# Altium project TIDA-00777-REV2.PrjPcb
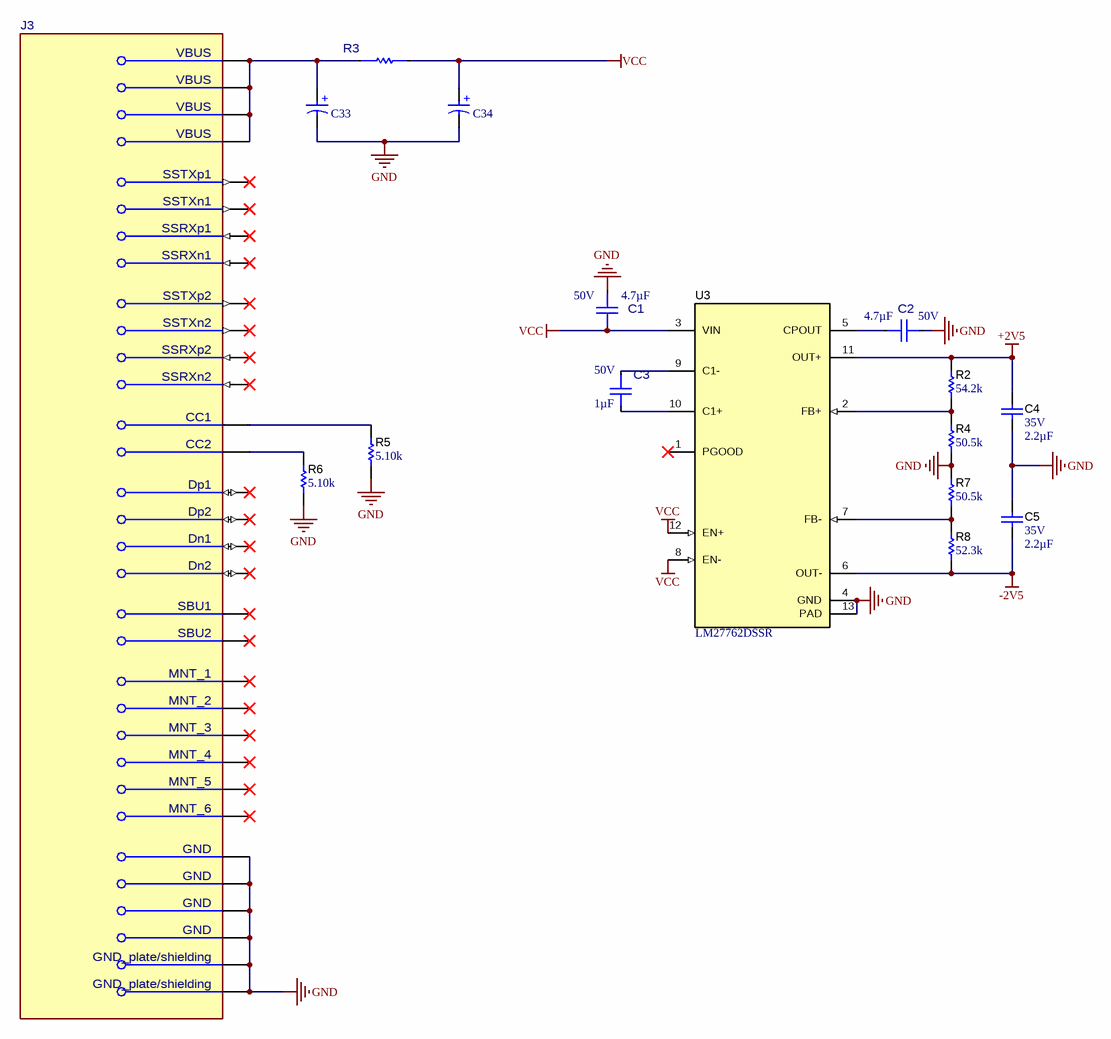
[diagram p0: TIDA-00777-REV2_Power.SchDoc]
CopyrightYear: 2018; PCB_Layout: Who did the Layout?; PCB_Rev: E1; PRJ_Customer: Public Release; PRJ_Engineer: Enter name of project lead; PRJ_Number: XXX###; PRJ_Title: Change in menu Project|Project Options|Parameters; SCH_Rev: E1; TechSupport: http://www.ti.com/support; TID: N/A
2 sheets, 105 parts. Net scope: global (net labels, ports and power ports of the same name join across sheets).
Board file: TIDA-00777-REV2.PcbDoc
Sheets:
  TIDA-00777-REV2_Power.SchDoc
  TIDA-00777-REV2_AFE.SchDoc

## Sheet TIDA-00777-REV2_Power.SchDoc
size 431 x 279 mm; Date: Not shown in title block; ApprovedBy: Not shown in title block; CheckedBy: Not shown in title block; Author: Not shown in title block; CompanyName: Not shown in title block; Engineer: Not shown in title block; Organization: Not shown in title block; Address1: Not shown in title block; Address2: Not shown in title block; Address3: Not shown in title block; Address4: Not shown in title block; DocumentNumber: 2; Revision: Use project parameter SCH_Rev; SheetNumber: 2; SheetTotal: 4; PageSetup: Record=PageOptions¦CenterHorizontal=True¦CenterVertical=True¦PrintScale=1.00¦XCorrection=1.00¦YCorrection=1.00¦PrintKind=0¦BorderSize=5000000¦LeftOffset=0¦BottomOffset=0¦Orientation=2¦PaperLength=1000¦PaperWidth=1000¦Scale=100¦PaperSource=15¦PrintQuality=600¦MediaType=1¦DitherType=10¦PaperKind=Letter¦PrintScaleMode=1

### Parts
(Parts that share a designator on the sheet are numbered #1, #2 ... from top to bottom, then left to right.)
C1  Cap_F: 4.7µF  VDC_V: 50V  [FP-CGA4J1X7R1H475K125AC_0805-MFG]  (hidden comment: CGA4J1X7R1H475K125AC)
C2  Cap_F: 4.7µF  VDC_V: 50V  [FP-CGA4J1X7R1H475K125AC_0805-MFG]  (hidden comment: CGA4J1X7R1H475K125AC)
C3  VDC_V: 50V  Cap_F: 1µF  [FP-GMC10X7R105K50NT_0603-MFG]  (hidden comment: GMC10X7R105K50NT)
C4  VDC_V: 35V  Cap_F: 2.2µF  [0603]  (hidden comment: C1608X5R1V225K080AC)
C5  VDC_V: 35V  Cap_F: 2.2µF  [0603]  (hidden comment: C1608X5R1V225K080AC)
C33  860020572003  [WCAP-ATG5_D5H11]  (value not drawn)
C34  860020572003  [WCAP-ATG5_D5H11]  (value not drawn)
J3#1  632723300011  [FP-632723300011_CONN_USB_8MM74_11MM20-MFG]  (value not drawn)
R2  ValueDisplayed: 54.2k  [0603]  (hidden comment: RT0603BRD0754K2L)
R3  RC0603JR-130RP  [FP-RC0603JR-130RP_0603-MFG]  (value not drawn)
R4  ValueDisplayed: 50.5k  [0603]  (hidden comment: RT0603DRE0750K5L)
R5  ValueDisplayed: 5.10k  [0603]  (hidden comment: RG1608P-512-B-T5)
R6  ValueDisplayed: 5.10k  [0603]  (hidden comment: RG1608P-512-B-T5)
R7  ValueDisplayed: 50.5k  [0603]  (hidden comment: RT0603DRE0750K5L)
R8  ValueDisplayed: 52.3k  [0603]  (hidden comment: RT0603BRD0752K3L)
U3  LM27762DSSR  [DSS0012B]

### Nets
+2V5: C4.1 R2.1 U3.11(OUT+)
-2V5: C5.2 R8.2 U3.6(OUT-)
GND: C1.1 C2.2 C4.2 C5.1 C33.2(N) C34.2(N) J3#1.1(GND_plate/shielding) J3#1.2(GND_plate/shielding) J3#1.A1(GND) J3#1.A12(GND) J3#1.B1(GND) J3#1.B12(GND) R4.1 R5.2 R6.2 R7.2 U3.4(GND) U3.13(PAD)
VCC: C1.2 C34.1(P) R3.2 U3.3(VIN) U3.8(EN-) U3.12(EN+)
NetC2_1: C2.1 U3.5(CPOUT)
NetC3_1: C3.1 U3.9(C1-)
NetC3_2: C3.2 U3.10(C1+)
NetC33_1: C33.1(P) J3#1.A4(VBUS) J3#1.A9(VBUS) J3#1.B4(VBUS) J3#1.B9(VBUS) R3.1
NetJ3#1_A5: J3#1.A5(CC1) R5.1
NetJ3#1_B5: J3#1.B5(CC2) R6.1
NetR2_2: R2.2 R4.2 U3.2(FB+)
NetR7_1: R7.1 R8.1 U3.7(FB-)

Not connected (* = marked no-connect by the designer): J3#1 3(MNT_1)* 4(MNT_2)* 5(MNT_3)* 6(MNT_4)* 7(MNT_5)* 8(MNT_6)* A2(SSTXp1)* A3(SSTXn1)* A6(Dp1)* A7(Dn1)* A8(SBU1)* A10(SSRXn2)* A11(SSRXp2)* B2(SSTXp2)* B3(SSTXn2)* B6(Dp2)* B7(Dn2)* B8(SBU2)* B10(SSRXn1)* B11(SSRXp1)*; U3 1(PGOOD)*

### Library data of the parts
C1 C2 = CMP-0090082-1: Cap Ceramic 4.7uF 50V X7R 10% Pad SMD 0805 +125°C Automotive T/R; Manufacturer: TDK Corporation; TempCo: 15%; Value: 4.7µF; Tolerance_%: 0.1%; SizeZ_mm: 1.45mm; AEC Qualified: Yes; AEC Grade: Grade 1
C3 = CMP-0095295-1: 1 µF ±10% 50V Ceramic Capacitor X7R 0603 (1608 Metric); Manufacturer: Cal-Chip Electronics; TempCo: 30ppm/°C; Value: 1µF; SizeZ_mm: 1mm; AEC Qualified: No; ValueDisplayed: 1uF
C4 C5 = CMP-0007020-5: CAP, CERM, 2.2 uF, 35 V, +/- 10%, X5R, 0603; Manufacturer: TDK; TaMin_C: -55°C; Polarized: N; SizeAreaWB_mm2: 4.68; Value1: 0.007674 ohm; U/M: EA; Value: 2.2uF; TaMax_C: 85°C; SizeZ_mm: 1; SizeX_mm: 1.6; SizeY_mm: 0.8; SizeArea_mm2: 1.28; AEC Category: Q200; ESR_ohm: 7.674m; IRMS_A: 1.8782A
C33 C34 = CMP-0109532-1: WCAP-ATG5 Aluminum Electrolytic Capacitor, Radial, THT, D5 x H11mm, 10µF, 35V; Manufacturer: Wurth Elektronik; Capacitance Tolerance: +/-20%; Dissipation Factor: 12%; Endurance: 2000h; Leakage Current: 3.5uA; Ripple Current: 46mA; Technical Reference: ATDC110100M035DSPA3B000
J3#1 = CMP-0091586-1: USB-C (USB TYPE-C) USB 3.2 Gen 2 (USB 3.1 Gen 2, Superspeed + (USB 3.1)) Receptacle Connector 24 Position Surface Mount, Right Angle; Through Hole; Manufacturer: Wurth; AEC Qualified: No; Shrouded: true; SizeZ_mm: 3.41mm; Is Female: yes; Usb Standard: USB 3.1; Voltage_V: 20V; ContactFinish: Gold,Nickel; Conn Orientation: Horizontal; Standoff Height: 0.1mm; Current_A: 5A
R2 = CMP-0024333-2: RES, 54.2 k, 0.1%, 0.1 W, 0603; Manufacturer: Yageo America; Power_W: 100mW; TempCo: 25 ppm/C; Value_Code: 54k2; Value: 54.2k; EIA_Code: E192; SizeX_mm: 1.6; SizeY_mm: 0.8; SizeZ_mm: 1; Value2: 0.1W; SizeArea_mm2: 1.28; VDC_V: 75V; AEC Category: Q200; U/M: EA
R3 = CMP-0120804-1: Resistor Thick Film 0603 Jumper 0 Ohm ±5% 1/10W Molded Paper T/R; Manufacturer: Yageo; Power_W: 100mW; Value: 0; SizeZ_mm: 0.55mm; AEC Qualified: No; VDC_V: 75V
R4 R7 = CMP-0025375-2: RES, 50.5 k, 0.5%, 0.1 W, 0603; Manufacturer: Yageo America; Power_W: 100mW; TempCo: 50 ppm/C; Value_Code: 50k5; U/M: EA; Value: 50.5k; EIA_Code: E192; SizeX_mm: 1.6; SizeY_mm: 0.8; SizeZ_mm: 1; Value2: 0.1W; SizeArea_mm2: 1.28; VDC_V: 75V; AEC Category: Q200
R5 R6 = CMP-0023568-3: RES, 5.10 k, 0.1%, 0.1 W, 0603; Manufacturer: Susumu Co Ltd; Power_W: 100mW; TempCo: 25 ppm/C; Value_Code: 5k10; Value: 5.10k; Res_ohm: 5.1k; SizeX_mm: 1.6; SizeY_mm: 0.8; SizeZ_mm: 1; Value2: 0.1W; SizeArea_mm2: 1.28; VDC_V: 75V; AEC Category: Q200; U/M: EA
R8 = CMP-0024319-3: RES, 52.3 k, 0.1%, 0.1 W, 0603; Manufacturer: Yageo America; Power_W: 100mW; TempCo: 25 ppm/C; Value_Code: 52k3; U/M: EA; Value: 52.3k; EIA_Code: E192; SizeX_mm: 1.6; SizeY_mm: 0.8; SizeZ_mm: 1; Value2: 0.1W; SizeArea_mm2: 1.28; VDC_V: 75V; AEC Category: Q200
U3 = CMP-0076280-3: Low-Noise Positive- and Negative-Output Charge Pump With Integrated LDO, DSS0012B (WSON-12); Alternate PartNumber: LM27762DSST; Alternate Manufacturer: Texas Instruments; SizeZ_mm: 0.8; SizeArea_mm2: 6.0; AEC Qualified: N; Rating: Catalog; SizeY_mm: 3.0; SizeX_mm: 2.0; CompType: IC; AEC Category: Q200; SizeAreaWB_mm2: 12.0

## Sheet TIDA-00777-REV2_AFE.SchDoc
size 431 x 279 mm; Date: Not shown in title block; ApprovedBy: Not shown in title block; CheckedBy: Not shown in title block; Author: Not shown in title block; CompanyName: Not shown in title block; Engineer: Not shown in title block; Organization: Not shown in title block; Address1: Not shown in title block; Address2: Not shown in title block; Address3: Not shown in title block; Address4: Not shown in title block; DocumentNumber: 2; Revision: Use project parameter SCH_Rev; SheetNumber: 3; SheetTotal: 4; PageSetup: Record=PageOptions¦CenterHorizontal=True¦CenterVertical=True¦PrintScale=1.00¦XCorrection=1.00¦YCorrection=1.00¦PrintKind=0¦BorderSize=5000000¦LeftOffset=0¦BottomOffset=0¦Orientation=2¦PaperLength=1000¦PaperWidth=1000¦Scale=100¦PaperSource=15¦PrintQuality=600¦MediaType=1¦DitherType=10¦PaperKind=Letter¦PrintScaleMode=1
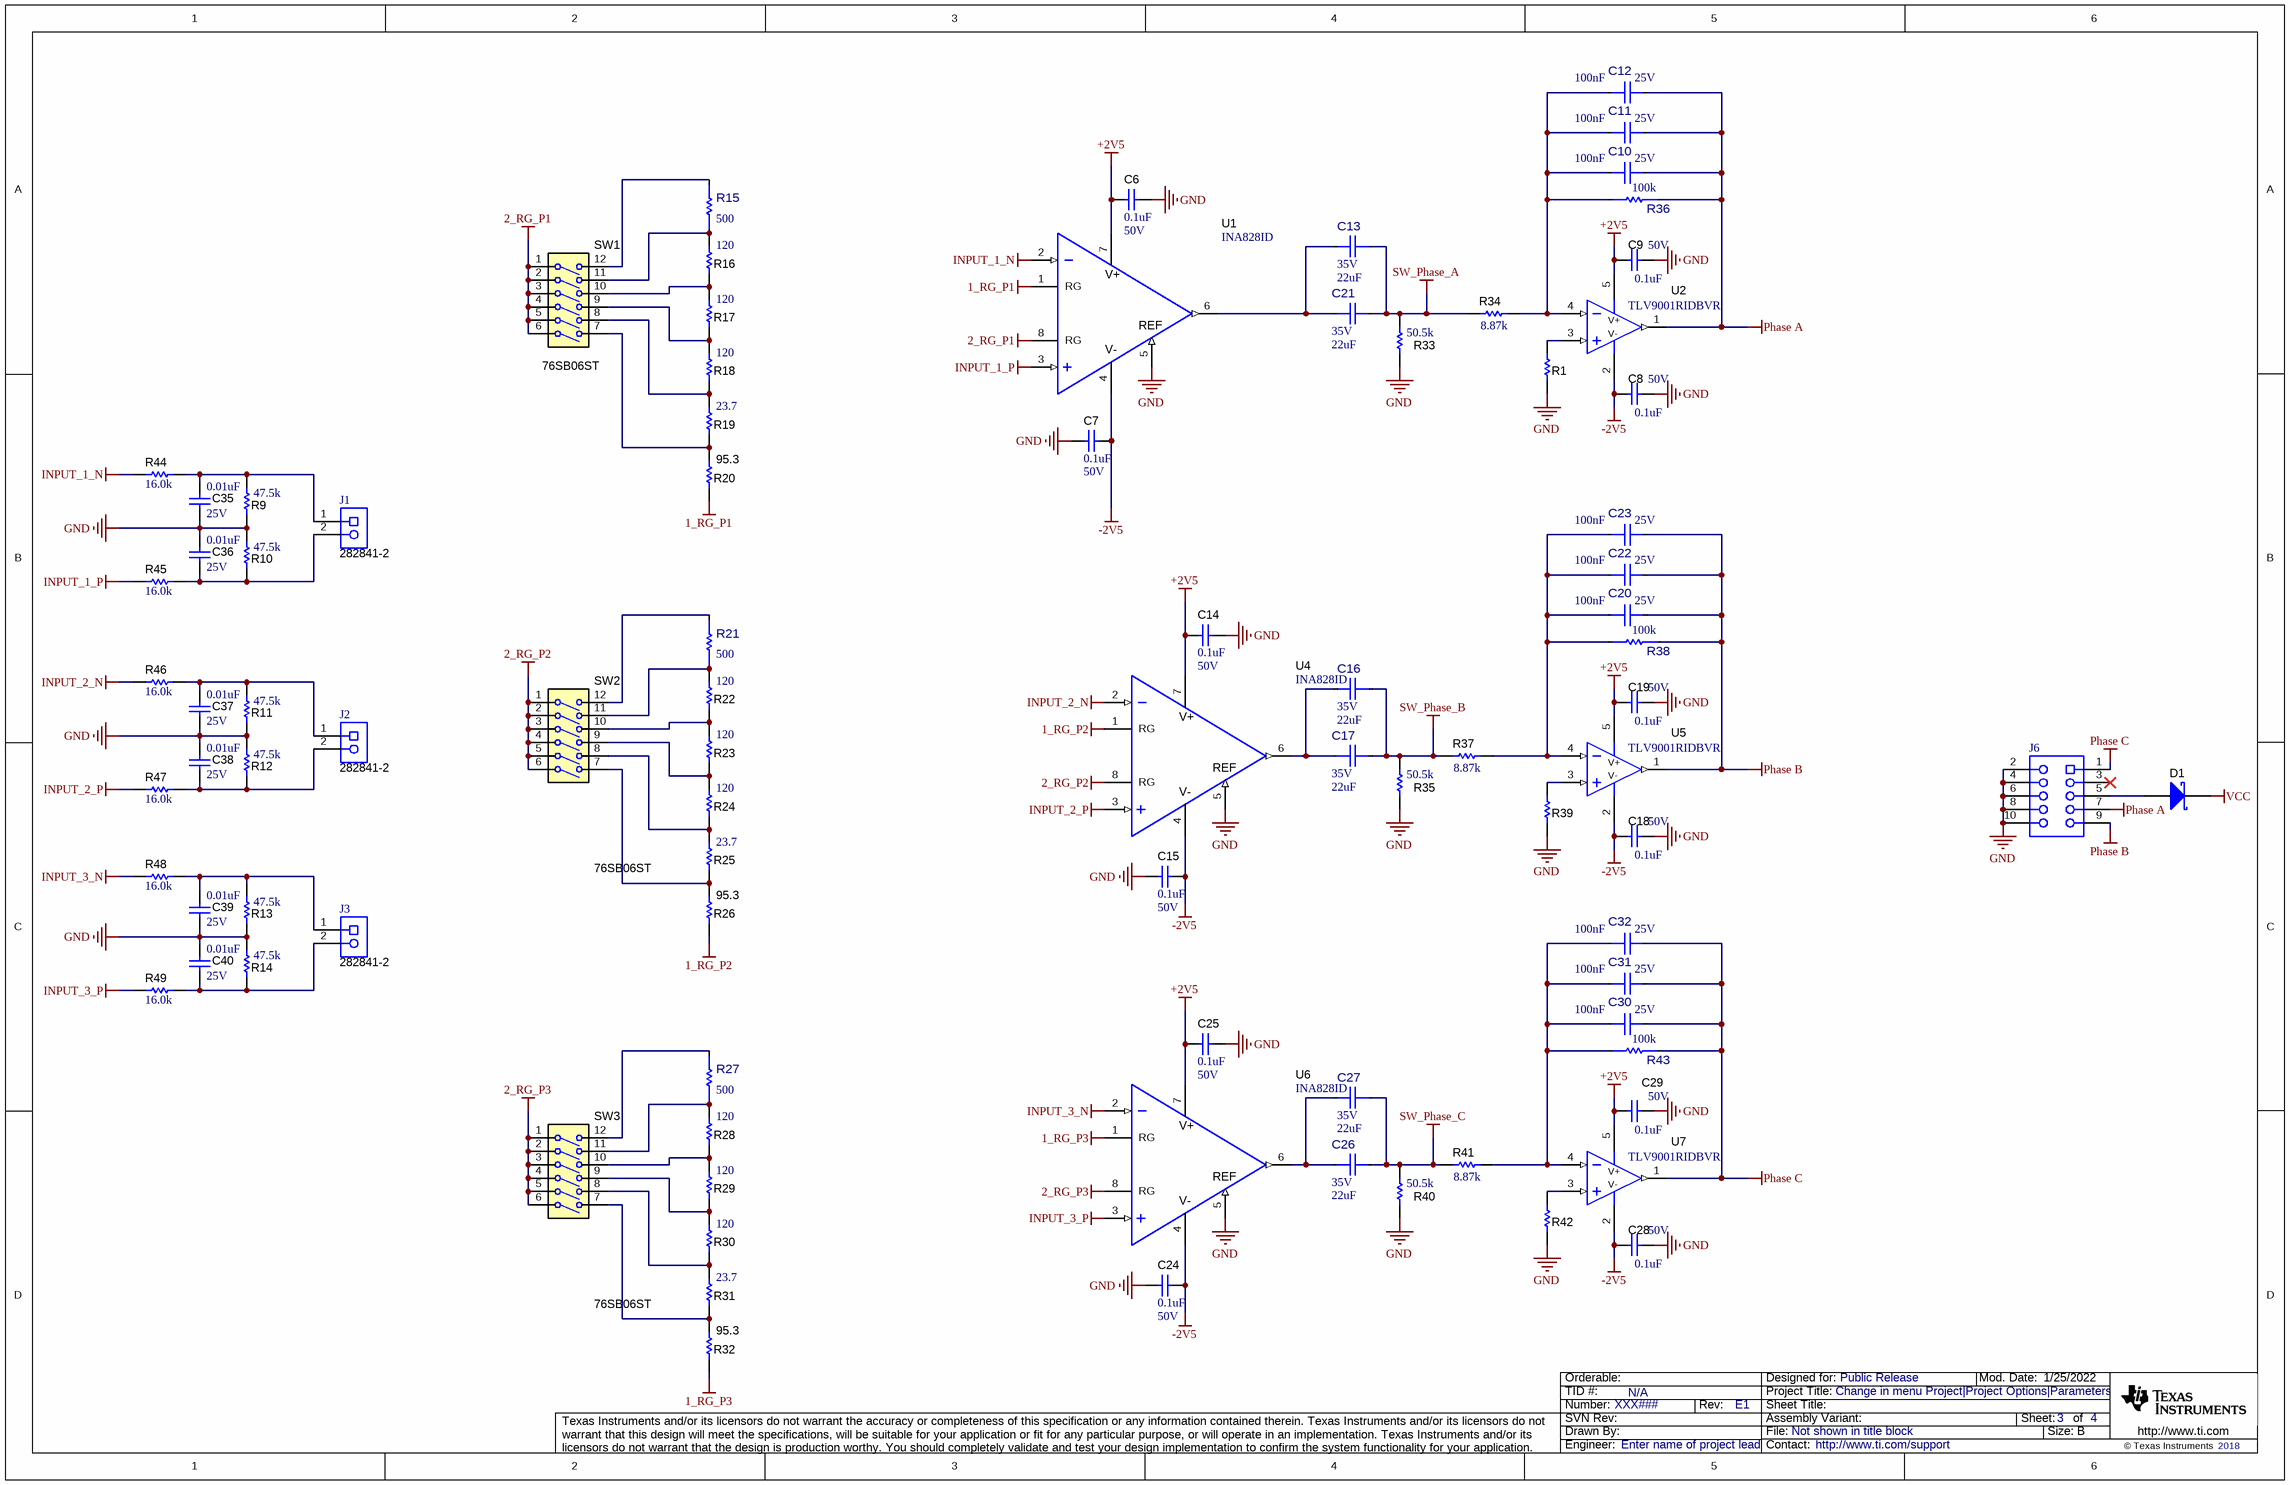
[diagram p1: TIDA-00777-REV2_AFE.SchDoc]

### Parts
(Parts that share a designator on the sheet are numbered #1, #2 ... from top to bottom, then left to right.)
C6  value 0.1uF  VDC_V: 50V  [0603]  (hidden comment: 06035C104JAT2A)
C7  value 0.1uF  VDC_V: 50V  [0603]  (hidden comment: 06035C104JAT2A)
C8  value 0.1uF  VDC_V: 50V  [0603]  (hidden comment: 06035C104JAT2A)
C9  value 0.1uF  VDC_V: 50V  [0603]  (hidden comment: 06035C104JAT2A)
C10  value 100nF  VDC_V: 25V  [FP-AC0805KRX7R8BB104_0805-MFG]  (hidden comment: AC0805KRX7R8BB104)
C11  value 100nF  VDC_V: 25V  [FP-AC0805KRX7R8BB104_0805-MFG]  (hidden comment: AC0805KRX7R8BB104)
C12  value 100nF  VDC_V: 25V  [FP-AC0805KRX7R8BB104_0805-MFG]  (hidden comment: AC0805KRX7R8BB104)
C13  VDC_V: 35V  ValueDisplayed: 22uF  [FP-GMC21X5R226M35NT_0805-MFG]  (hidden comment: GMC21X5R226M35NT)
C14  value 0.1uF  VDC_V: 50V  [0603]  (hidden comment: 06035C104JAT2A)
C15  value 0.1uF  VDC_V: 50V  [0603]  (hidden comment: 06035C104JAT2A)
C16  VDC_V: 35V  ValueDisplayed: 22uF  [FP-GMC21X5R226M35NT_0805-MFG]  (hidden comment: GMC21X5R226M35NT)
C17  VDC_V: 35V  ValueDisplayed: 22uF  [FP-GMC21X5R226M35NT_0805-MFG]  (hidden comment: GMC21X5R226M35NT)
C18  value 0.1uF  VDC_V: 50V  [0603]  (hidden comment: 06035C104JAT2A)
C19  value 0.1uF  VDC_V: 50V  [0603]  (hidden comment: 06035C104JAT2A)
C20  value 100nF  VDC_V: 25V  [FP-AC0805KRX7R8BB104_0805-MFG]  (hidden comment: AC0805KRX7R8BB104)
C21  VDC_V: 35V  ValueDisplayed: 22uF  [FP-GMC21X5R226M35NT_0805-MFG]  (hidden comment: GMC21X5R226M35NT)
C22  value 100nF  VDC_V: 25V  [FP-AC0805KRX7R8BB104_0805-MFG]  (hidden comment: AC0805KRX7R8BB104)
C23  value 100nF  VDC_V: 25V  [FP-AC0805KRX7R8BB104_0805-MFG]  (hidden comment: AC0805KRX7R8BB104)
C24  value 0.1uF  VDC_V: 50V  [0603]  (hidden comment: 06035C104JAT2A)
C25  value 0.1uF  VDC_V: 50V  [0603]  (hidden comment: 06035C104JAT2A)
C26  VDC_V: 35V  ValueDisplayed: 22uF  [FP-GMC21X5R226M35NT_0805-MFG]  (hidden comment: GMC21X5R226M35NT)
C27  VDC_V: 35V  ValueDisplayed: 22uF  [FP-GMC21X5R226M35NT_0805-MFG]  (hidden comment: GMC21X5R226M35NT)
C28  value 0.1uF  VDC_V: 50V  [0603]  (hidden comment: 06035C104JAT2A)
C29  value 0.1uF  VDC_V: 50V  [0603]  (hidden comment: 06035C104JAT2A)
C30  value 100nF  VDC_V: 25V  [FP-AC0805KRX7R8BB104_0805-MFG]  (hidden comment: AC0805KRX7R8BB104)
C31  value 100nF  VDC_V: 25V  [FP-AC0805KRX7R8BB104_0805-MFG]  (hidden comment: AC0805KRX7R8BB104)
C32  value 100nF  VDC_V: 25V  [FP-AC0805KRX7R8BB104_0805-MFG]  (hidden comment: AC0805KRX7R8BB104)
C35  value 0.01uF  VDC_V: 25V  [0603]  (hidden comment: C0603H103J3GACTU)
C36  value 0.01uF  VDC_V: 25V  [0603]  (hidden comment: C0603H103J3GACTU)
C37  value 0.01uF  VDC_V: 25V  [0603]  (hidden comment: C0603H103J3GACTU)
C38  value 0.01uF  VDC_V: 25V  [0603]  (hidden comment: C0603H103J3GACTU)
C39  value 0.01uF  VDC_V: 25V  [0603]  (hidden comment: C0603H103J3GACTU)
C40  value 0.01uF  VDC_V: 25V  [0603]  (hidden comment: C0603H103J3GACTU)
D1  SD103AWS-7-F  [SOD-323]  (value not drawn)
J1  282841-2  [TEC_282841-2]
J2  282841-2  [TEC_282841-2]
J3#2  282841-2  [TEC_282841-2]
J6  SFH11-PBPC-D05-RA-BK  [Sullins_SFH11-PBPC-D05-RA-BK]  (value not drawn)
R1  RT0603BRD079K88L  [0603]  (value not drawn)
R9  value 47.5k  [0603]  (hidden comment: RT0603BRD0747K5L)
R10  value 47.5k  [0603]  (hidden comment: RT0603BRD0747K5L)
R11  value 47.5k  [0603]  (hidden comment: RT0603BRD0747K5L)
R12  value 47.5k  [0603]  (hidden comment: RT0603BRD0747K5L)
R13  value 47.5k  [0603]  (hidden comment: RT0603BRD0747K5L)
R14  value 47.5k  [0603]  (hidden comment: RT0603BRD0747K5L)
R15  value 500  [FP-MCT06030D5000BP100_0603-MFG]  (hidden comment: MCT06030D5000BP100)
R16  value 120  [0603]  (hidden comment: RT0603BRD07120RL)
R17  value 120  [0603]  (hidden comment: RT0603BRD07120RL)
R18  value 120  [0603]  (hidden comment: RT0603BRD07120RL)
R19  value 23.7  [0603]  (hidden comment: RT0603BRD0723R7L)
R20  95.3  [0603]
R21  value 500  [FP-MCT06030D5000BP100_0603-MFG]  (hidden comment: MCT06030D5000BP100)
R22  value 120  [0603]  (hidden comment: RT0603BRD07120RL)
R23  value 120  [0603]  (hidden comment: RT0603BRD07120RL)
R24  value 120  [0603]  (hidden comment: RT0603BRD07120RL)
R25  value 23.7  [0603]  (hidden comment: RT0603BRD0723R7L)
R26  95.3  [0603]
R27  value 500  [FP-MCT06030D5000BP100_0603-MFG]  (hidden comment: MCT06030D5000BP100)
R28  value 120  [0603]  (hidden comment: RT0603BRD07120RL)
R29  value 120  [0603]  (hidden comment: RT0603BRD07120RL)
R30  value 120  [0603]  (hidden comment: RT0603BRD07120RL)
R31  value 23.7  [0603]  (hidden comment: RT0603BRD0723R7L)
R32  95.3  [0603]
R33  value 50.5k  [0603]  (hidden comment: RT0603BRD0750K5L)
R34  value 8.87k  [0603]  (hidden comment: RT0603BRD078K87L)
R35  value 50.5k  [0603]  (hidden comment: RT0603BRD0750K5L)
R36  value 100k  [FP-ERA-3AEB104V_0603-MFG]  (hidden comment: ERA-3AEB104V)
R37  value 8.87k  [0603]  (hidden comment: RT0603BRD078K87L)
R38  value 100k  [FP-ERA-3AEB104V_0603-MFG]  (hidden comment: ERA-3AEB104V)
R39  RT0603BRD079K88L  [0603]  (value not drawn)
R40  value 50.5k  [0603]  (hidden comment: RT0603BRD0750K5L)
R41  value 8.87k  [0603]  (hidden comment: RT0603BRD078K87L)
R42  RT0603BRD079K88L  [0603]  (value not drawn)
R43  value 100k  [FP-ERA-3AEB104V_0603-MFG]  (hidden comment: ERA-3AEB104V)
R44  value 16.0k  [0603]  (hidden comment: RT0603BRD0716KL)
R45  value 16.0k  [0603]  (hidden comment: RT0603BRD0716KL)
R46  value 16.0k  [0603]  (hidden comment: RT0603BRD0716KL)
R47  value 16.0k  [0603]  (hidden comment: RT0603BRD0716KL)
R48  value 16.0k  [0603]  (hidden comment: RT0603BRD0716KL)
R49  value 16.0k  [0603]  (hidden comment: RT0603BRD0716KL)
SW1  76SB06ST  [SW_76SB06]
SW2  76SB06ST  [SW_76SB06]
SW3  76SB06ST  [SW_76SB06]
U1  INA828ID  [D0008A_N]
U2  TLV9001RIDBVR  [DBV0005A_N]
U4  INA828ID  [D0008A_N]
U5  TLV9001RIDBVR  [DBV0005A_N]
U6  INA828ID  [D0008A_N]
U7  TLV9001RIDBVR  [DBV0005A_N]

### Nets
1_RG_P1: R20.2 U1.1(RG)
1_RG_P2: R26.2 U4.1(RG)
1_RG_P3: R32.2 U6.1(RG)
2_RG_P1: SW1.1 SW1.2 SW1.3 SW1.4 SW1.5 SW1.6 U1.8(RG)
2_RG_P2: SW2.1 SW2.2 SW2.3 SW2.4 SW2.5 SW2.6 U4.8(RG)
2_RG_P3: SW3.1 SW3.2 SW3.3 SW3.4 SW3.5 SW3.6 U6.8(RG)
+2V5: C6.2 C9.2 C14.2 C19.2 C25.2 C29.2 U1.7(V+) U2.5(V+) U4.7(V+) U5.5(V+) U6.7(V+) U7.5(V+)
-2V5: C7.1 C8.2 C15.1 C18.2 C24.1 C28.2 U1.4(V-) U2.2(V-) U4.4(V-) U5.2(V-) U6.4(V-) U7.2(V-)
GND: C6.1 C7.2 C8.1 C9.1 C14.1 C15.2 C18.1 C19.1 C24.2 C25.1 C28.1 C29.1 C35.2 C36.1 C37.2 C38.1 C39.2 C40.1 J6.2 J6.4 J6.6 J6.8 J6.10 R1.1 R9.1 R10.2 R11.1 R12.2 R13.1 R14.2 R33.2 R35.2 R39.1 R40.2 R42.1 U1.5(REF) U4.5(REF) U6.5(REF)
INPUT_1_N: R44.2 U1.2(IN-)
INPUT_1_P: R45.2 U1.3(IN+)
INPUT_2_N: R46.2 U4.2(IN-)
INPUT_2_P: R47.2 U4.3(IN+)
INPUT_3_N: R48.2 U6.2(IN-)
INPUT_3_P: R49.2 U6.3(IN+)
Phase A: C10.2 C11.2 C12.2 J6.7 R36.1 U2.1(OUT)
Phase B: C20.2 C22.2 C23.2 J6.9 R38.1 U5.1(OUT)
Phase C: C30.2 C31.2 C32.2 J6.1 R43.1 U7.1(OUT)
SW_Phase_A: C13.1 C21.2 R33.1 R34.1
SW_Phase_B: C16.1 C17.2 R35.1 R37.1
SW_Phase_C: C26.2 C27.1 R40.1 R41.1
VCC: D1.1(K)
NetC10_1: C10.1 C11.1 C12.1 R34.2 R36.2 U2.4(IN-)
NetC13_2: C13.2 C21.1 U1.6(OUT)
NetC16_2: C16.2 C17.1 U4.6(OUT)
NetC20_1: C20.1 C22.1 C23.1 R37.2 R38.2 U5.4(IN-)
NetC26_1: C26.1 C27.2 U6.6(OUT)
NetC30_1: C30.1 C31.1 C32.1 R41.2 R43.2 U7.4(IN-)
NetC35_1: C35.1 J1.1 R9.2 R44.1
NetC36_2: C36.2 J1.2 R10.1 R45.1
NetC37_1: C37.1 J2.1 R11.2 R46.1
NetC38_2: C38.2 J2.2 R12.1 R47.1
NetC39_1: C39.1 J3#2.1 R13.2 R48.1
NetC40_2: C40.2 J3#2.2 R14.1 R49.1
NetD1_2: D1.2(A) J6.5
NetR1_2: R1.2 U2.3(IN+)
NetR15_1: R15.1 R16.2 SW1.11(2A)
NetR15_2: R15.2 SW1.12(1A)
NetR16_1: R16.1 R17.2 SW1.10(3A)
NetR17_1: R17.1 R18.2 SW1.9(4A)
NetR18_1: R18.1 R19.2 SW1.8(5A)
NetR19_1: R19.1 R20.1 SW1.7(6A)
NetR21_1: R21.1 R22.2 SW2.11(2A)
NetR21_2: R21.2 SW2.12(1A)
NetR22_1: R22.1 R23.2 SW2.10(3A)
NetR23_1: R23.1 R24.2 SW2.9(4A)
NetR24_1: R24.1 R25.2 SW2.8(5A)
NetR25_1: R25.1 R26.1 SW2.7(6A)
NetR27_1: R27.1 R28.2 SW3.11(2A)
NetR27_2: R27.2 SW3.12(1A)
NetR28_1: R28.1 R29.2 SW3.10(3A)
NetR29_1: R29.1 R30.2 SW3.9(4A)
NetR30_1: R30.1 R31.2 SW3.8(5A)
NetR31_1: R31.1 R32.1 SW3.7(6A)
NetR39_2: R39.2 U5.3(IN+)
NetR42_2: R42.2 U7.3(IN+)

Not connected (* = marked no-connect by the designer): J6 3*

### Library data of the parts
C6-C9 C14 C15 C18 C19 C24 C25 C28 C29 = CMP-0083854-1: CAP, CERM, 0.1 µF, 50 V,+/- 5%, X7R, 0603; Manufacturer: AVX; SizeZ_mm: 1; AEC Qualified: N; Cap_F: 100nF; ValueDisplayed: 0.1µF; TaMin_C: -55°C; Green_Lifecycle: Active; SizeAreaWB_mm2: 4.68; Green_REACh: Passed; U/M: EA; TaMax_C: 125°C; SizeX_mm: 1.6; SizeY_mm: 0.8; SizeArea_mm2: 1.28; AEC Category: Q200
C10-C12 C20 C22 C23 C30-C32 = CMP-0121355-1: 0.1 µF ±10% 25V Ceramic Capacitor X7R 0805 (2012 Metric); Manufacturer: Yageo; TempCo: 15%; SizeZ_mm: 0.95mm; AEC Qualified: Yes; AEC Grade: Grade 1
C13 C16 C17 C21 C26 C27 = CMP-0120897-1: 22 µF ±20% 35V Ceramic Capacitor X5R 0805 (2012 Metric); Manufacturer: Cal-Chip Electronics; TempCo: 15%; Value: 22µF; SizeZ_mm: 1.45mm; AEC Qualified: No
C35-C40 = CMP-0006975-4: CAP, CERM, 0.01 uF, 25 V, +/- 5%, C0G/NP0, 0603; Manufacturer: Kemet; SizeZ_mm: 1; Cap_F: 10nF; TaMin_C: -55°C; Polarized: N; SizeAreaWB_mm2: 4.68; U/M: EA; TaMax_C: 200°C; SizeX_mm: 1.6; SizeY_mm: 0.8; SizeArea_mm2: 1.28; AEC Category: Q200; Value1: Unknown
D1 = CMP-0028544-2: Diode, Schottky, 40 V, 0.35 A, SOD-323; Manufacturer: Diodes Inc.; SizeY_mm: 1.35; Vf_V: 550mV; SizeArea_mm2: 3.645; Value: 40V; AEC Category: Q101; SizeZ_mm: 1; SizeAreaWB_mm2: 8.695; Value2: 0.55V; Io_A: 350mA; Value1: 0.35A; SizeX_mm: 2.7; Green_Lifecycle: Active; Green_REACh: Passed
J1 J2 J3#2 = CMP-0054973-1: Terminal Block, 2x1, 5.08mm, TH; Manufacturer: TE Connectivity; CNHeader: FALSE; Green_Lifecycle: Active; Green_REACh: Passed; CT: TRUE
J6 = CMP-0054694-1: Receptacle, 2.54mm, 5x2, Gold, R/A, TH; Manufacturer: Sullins Connector Solutions; CNHeader: FALSE; Current_A: 3A; Green_Lifecycle: Not Set; Gender: Female; Green_REACh: Incomplete; Voltage_V: 1kV; CompType: Socket Strip; Row_Count: 2; RowSpacing_mm: 2.54; CT: TRUE; Cert_UL: Y
R1 R39 R42 = CMP-0024558-2: RES, 9.88 k, 0.1%, 0.1 W, 0603; Manufacturer: Yageo America; Power_W: 100mW; TempCo: 25 ppm/C; Value_Code: 9k88; U/M: EA; Value: 9.88k; EIA_Code: E192; SizeX_mm: 1.6; SizeY_mm: 0.8; SizeZ_mm: 1; Value2: 0.1W; SizeArea_mm2: 1.28; VDC_V: 75V; AEC Category: Q200
R9-R14 = CMP-0024266-3: RES, 47.5 k, 0.1%, 0.1 W, 0603; Manufacturer: Yageo America; Power_W: 100mW; TempCo: 25 ppm/C; Value_Code: 47k5; U/M: EA; EIA_Code: E192; SizeX_mm: 1.6; SizeY_mm: 0.8; SizeZ_mm: 1; Value2: 0.1W; SizeArea_mm2: 1.28; VDC_V: 75V; AEC Category: Q200
R15 R21 R27 = CMP-0121720-1: Res Thin Film 0603 500Ω 0.1% 0.1W ±25ppm/°C Molded SMD Paper  T/R; Manufacturer: Vishay; Power_W: 100mW; SizeZ_mm: 0.55mm; AEC Qualified: No; VDC_V: 75V
R16-R18 R22-R24 R28-R30 = CMP-0023691-3: RES, 120, 0.1%, 0.1 W, 0603; Manufacturer: Yageo America; Power_W: 100mW; TempCo: 25 ppm/C; Value_Code: 120R; U/M: EA; EIA_Code: E192; SizeX_mm: 1.6; SizeY_mm: 0.8; SizeZ_mm: 1; Value2: 0.1W; SizeArea_mm2: 1.28; VDC_V: 75V; AEC Category: Q200
R19 R25 R31 = CMP-0023979-3: RES, 23.7, 0.1%, 0.1 W, 0603; Manufacturer: Yageo America; Power_W: 100mW; TempCo: 25 ppm/C; Value_Code: 23R7; U/M: EA; EIA_Code: E192; SizeX_mm: 1.6; SizeY_mm: 0.8; SizeZ_mm: 1; Value2: 0.1W; SizeArea_mm2: 1.28; VDC_V: 75V; AEC Category: Q200
R20 R26 R32 = CMP-0024541-2: RES, 95.3, 0.1%, 0.1 W, 0603; Manufacturer: Yageo America; PartNumber: RT0603BRD0795R3L; Power_W: 100mW; TempCo: 25 ppm/C; Value_Code: 95R3; U/M: EA; EIA_Code: E192; SizeX_mm: 1.6; SizeY_mm: 0.8; SizeZ_mm: 1; Value2: 0.1W; SizeArea_mm2: 1.28; VDC_V: 75V; AEC Category: Q200
R33 R35 R40 = CMP-0024307-2: RES, 50.5 k, 0.1%, 0.1 W, 0603; Manufacturer: Yageo America; Power_W: 100mW; TempCo: 25 ppm/C; Value_Code: 50k5; EIA_Code: E192; SizeX_mm: 1.6; SizeY_mm: 0.8; SizeZ_mm: 1; Value2: 0.1W; SizeArea_mm2: 1.28; VDC_V: 75V; AEC Category: Q200; U/M: EA
R34 R37 R41 = CMP-0024525-2: RES, 8.87 k, 0.1%, 0.1 W, 0603; Manufacturer: Yageo America; Power_W: 100mW; TempCo: 25 ppm/C; Value_Code: 8k87; EIA_Code: E192; SizeX_mm: 1.6; SizeY_mm: 0.8; SizeZ_mm: 1; Value2: 0.1W; SizeArea_mm2: 1.28; VDC_V: 75V; AEC Category: Q200; U/M: EA
R36 R38 R43 = CMP-0046061-1: Res Thin Film 0603 100K Ohm 0.1% 0.1W ±25ppm/°C Molded SMD Punched Carrier T/R; Manufacturer: Panasonic; Power_W: 100mW; SizeZ_mm: 0.55mm; AEC Qualified: Yes; VDC_V: 75V; AEC Grade: Grade 0
R44-R49 = CMP-0023803-3: RES, 16.0 k, 0.1%, 0.1 W, 0603; Manufacturer: Yageo America; Power_W: 100mW; TempCo: 25 ppm/C; Value_Code: 16k0; U/M: EA; EIA_Code: E192; SizeX_mm: 1.6; SizeY_mm: 0.8; SizeZ_mm: 1; Value2: 0.1W; SizeArea_mm2: 1.28; VDC_V: 75V; AEC Category: Q200; Res_ohm: 16k
SW1-SW3 = CMP-0002309-1: Switch, SPST, Off-On, 6 Pos, 0.15 A, 30 VDC, TH; Manufacturer: Grayhill; PositionCount: 6; SizeZ_mm: 8.13; VDC_V: 30V; CurrentRating_mA: 150A; SizeX_mm: 9.65; SizeY_mm: 17.3; SizeArea_mm2: 166.945; SizeAreaWB_mm2: 224.845
U1 U4 U6 = CMP-0079943-1: 50-uV Offset, 7-nV/√Hz Noise, Low-Power, Precision Instrumentation Amplifier, D0008A (SOIC-8); Alternate PartNumber: INA828IDR; Alternate Manufacturer: Texas Instruments; SizeAreaWB_mm2: 56.58; SizeZ_mm: 1.75; SizeX_mm: 4.9; SizeY_mm: 6.2; SizeArea_mm2: 30.38; CompType: IC; AEC Qualified: N; AEC Category: Q200
U2 U5 U7 = CMP-0081555-1: Low-Power, Rail-to-Rail In and Out, 1-MHz Operational Amplifier, DBV0005A (SOT-23-5); Alternate PartNumber: TLV9001RIDBVT; Alternate Manufacturer: Texas Instruments; SizeAreaWB_mm2: 14.82; SizeZ_mm: 1.45; SizeX_mm: 2.8; SizeY_mm: 2.9; SizeArea_mm2: 8.12; CompType: IC; AEC Qualified: N; AEC Category: Q200

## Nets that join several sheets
+2V5: TIDA-00777-REV2_Power (C4.1 R2.1 U3.11), TIDA-00777-REV2_AFE (12 pins)
-2V5: TIDA-00777-REV2_Power (C5.2 R8.2 U3.6), TIDA-00777-REV2_AFE (12 pins)
GND: TIDA-00777-REV2_Power (18 pins), TIDA-00777-REV2_AFE (38 pins)
VCC: TIDA-00777-REV2_Power (6 pins), TIDA-00777-REV2_AFE (D1.1)

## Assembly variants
001: all parts fitted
